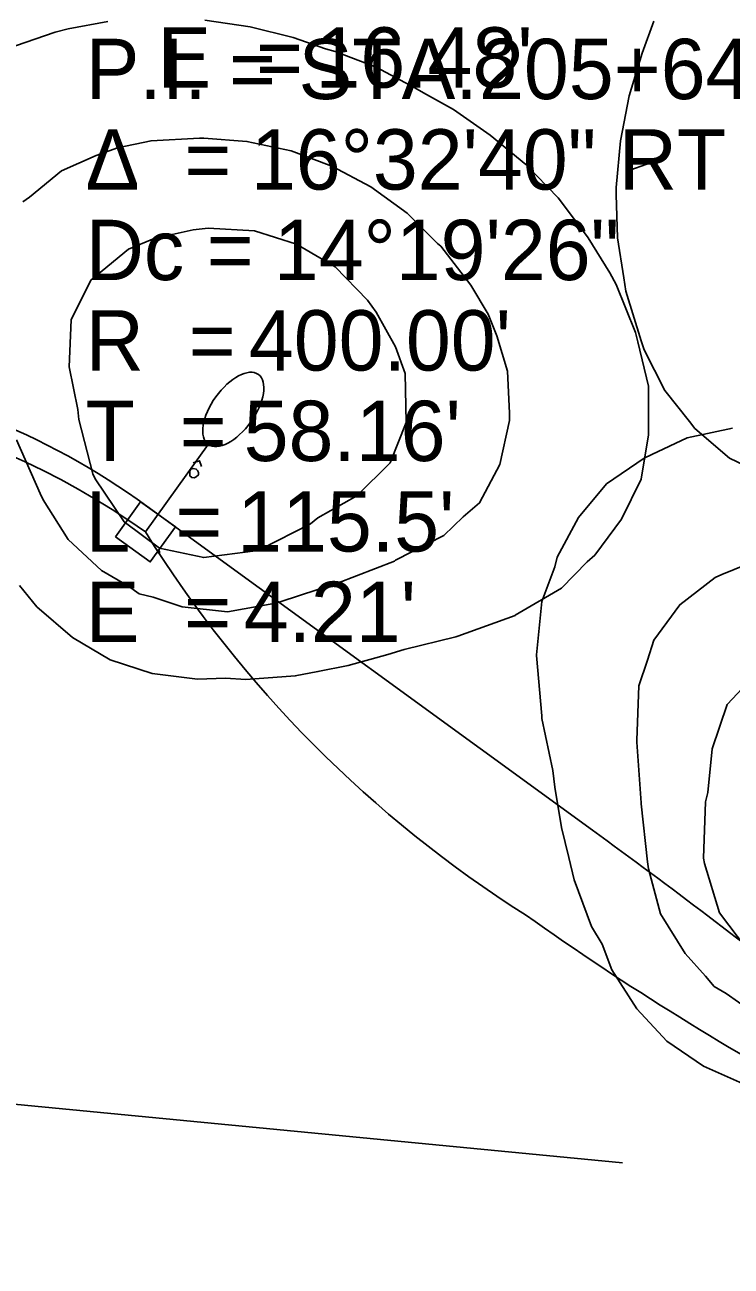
# Model space of a CAD drawing. Extents: x 1598538 to 1602183, y 285823 to 288192.
# Drawn here: x 1600950.3 to 1601032.3, y 286525.8 to 286669.9 of the extents above; entities that cross this region are included whole.
import ezdxf

# ---------------------------------------------------------------- set-up
doc = ezdxf.new("R2010")
doc.units = 0
for name, color, linetype in [('CM_Corridor_Conceptual', 7, 'Continuous'), ('Default', 7, 'Continuous'), ('MD_P_ACSC_T', 7, 'Continuous'), ('MD_P_AGB_B', 7, 'Continuous'), ('RW_P_Esmt_LA', 7, 'Continuous'), ('RW_P_Esmt_TMP', 7, 'Continuous')]:
    doc.layers.add(name, color=color, linetype=linetype)

msp = doc.modelspace()

# ---------------------------------------------------------------- linework, layer by layer
at = {"layer": 'Default'}
msp.add_line((1601016.17, 286576.42), (1600964.45, 286614.03), dxfattribs=at)
for points in [[(1600959.92, 286670.27), (1600955.3, 286669.4), (1600953.8, 286669.02), (1600948.05, 286667.05)], [(1600949.67, 286604.8), (1600951.67, 286602.33), (1600955.8, 286598.8), (1600960.17, 286596.21), (1600965.05, 286594.61), (1600970.3, 286593.96), (1600973.55, 286594.08), (1600975.92, 286593.9), (1600981.67, 286594.33), (1600984.3, 286594.83), (1600987.8, 286595.55), (1600992.42, 286596.8), (1600994.3, 286597.4), (1601000.3, 286598.86), (1601000.55, 286598.93), (1601007.17, 286601.33), (1601007.17, 286601.36), (1601012.55, 286604.49), (1601015.55, 286607.55), (1601016.42, 286608.33), (1601019.55, 286612.52), (1601021.8, 286617.15), (1601022.67, 286622.3), (1601022.67, 286623.3), (1601022.67, 286627.93), (1601021.42, 286633.08), (1601021.17, 286634.18), (1601018.92, 286639.74), (1601018.17, 286641.11), (1601015.67, 286645.18), (1601012.67, 286649.15), (1601012.17, 286649.8), (1601008.42, 286653.68), (1601004.3, 286657.08), (1601000.05, 286660.05), (1600996.55, 286661.99), (1600995.55, 286662.58), (1600991.05, 286664.96), (1600986.3, 286666.77), (1600985.17, 286667.11), (1600981.42, 286668.4), (1600976.42, 286669.65), (1600971.17, 286670.43)], [(1601023.3, 286670.3), (1601021.92, 286666.61), (1601020.42, 286661.65), (1601019.42, 286656.43), (1601018.92, 286650.99), (1601018.92, 286650.18), (1601019.05, 286645.18), (1601019.8, 286640.52), (1601020.05, 286638.99), (1601021.8, 286633.21), (1601022.17, 286632.18), (1601024.55, 286627.43), (1601027.42, 286623.83), (1601028.05, 286623.05), (1601032.05, 286619.61), (1601036.67, 286617.4)], [(1600949.3, 286621.74), (1600952.05, 286615.49), (1600952.42, 286614.74), (1600955.3, 286610.15), (1600959.17, 286606.55), (1600962.3, 286604.74), (1600963.55, 286603.86), (1600965.17, 286603.46), (1600968.55, 286602.36), (1600973.8, 286601.77), (1600979.17, 286602.74), (1600979.92, 286602.93), (1600986.42, 286605.05), (1600986.55, 286605.08), (1600993.17, 286607.65), (1600993.3, 286607.74), (1600998.92, 286610.61), (1601001.17, 286612.8), (1601003.05, 286614.4), (1601005.42, 286618.86), (1601006.55, 286623.96), (1601006.55, 286624.8), (1601006.3, 286629.68), (1601005.05, 286633.8), (1601004.05, 286636.3), (1601002.05, 286639.68), (1600998.55, 286644.18), (1600998.17, 286644.49), (1600994.67, 286648.02), (1600990.42, 286651.08), (1600985.92, 286653.46), (1600981.17, 286655.27), (1600976.05, 286656.36), (1600971.05, 286656.71), (1600970.55, 286656.74), (1600964.92, 286656.43), (1600961.05, 286655.61), (1600958.55, 286654.71), (1600954.55, 286652.93), (1600950.8, 286649.9), (1600950.05, 286649.33)], [(1601032.42, 286623.08), (1601027.17, 286621.96), (1601023.05, 286620.02), (1601022.17, 286619.61), (1601017.8, 286616.61), (1601014.55, 286612.71), (1601012.05, 286608.11), (1601011.8, 286606.99), (1601010.3, 286602.96), (1601009.67, 286596.77), (1601009.67, 286596.71), (1601010.3, 286589.71), (1601010.3, 286589.4), (1601011.55, 286583.33), (1601011.8, 286581.4), (1601012.55, 286576.74), (1601013.42, 286573.24), (1601014.05, 286570.68), (1601016.05, 286565.24), (1601017.3, 286563.18), (1601018.42, 286560.21), (1601021.3, 286555.71), (1601024.8, 286551.93), (1601029.05, 286549.02), (1601033.92, 286546.86)], [(1600969.8, 286619.05), (1600970.55, 286619.3), (1600970.8, 286618.61)], [(1600969.8, 286618.4), (1600969.55, 286618.3), (1600969.55, 286618.3), (1600969.8, 286618.4), (1600969.8, 286618.4)], [(1600970.17, 286617.43), (1600970.42, 286617.65), (1600970.42, 286617.65), (1600970.17, 286617.43), (1600970.17, 286617.43)], [(1600965.92, 286608.8), (1600965.67, 286608.9), (1600965.67, 286608.9), (1600965.92, 286608.8), (1600965.92, 286608.8)], [(1601035.67, 286607.9), (1601031.17, 286606.08), (1601030.42, 286605.74), (1601026.3, 286602.58), (1601023.3, 286598.46), (1601022.55, 286596.15), (1601021.55, 286593.18), (1601021.3, 286586.86), (1601021.3, 286586.65), (1601021.8, 286579.58), (1601021.8, 286579.49), (1601022.55, 286572.74), (1601022.67, 286571.93), (1601024.05, 286566.71), (1601026.92, 286562.11), (1601029.3, 286559.49), (1601030.3, 286558.3), (1601031.67, 286557.46), (1601034.55, 286555.46)], [(1601035.3, 286594.77), (1601031.8, 286591.02), (1601030.05, 286585.86), (1601029.55, 286580.8), (1601029.3, 286579.71), (1601029.05, 286573.18), (1601029.17, 286572.55), (1601030.92, 286566.83), (1601034.05, 286562.68)]]:
    msp.add_lwpolyline(points, dxfattribs=at)
for points in [[(1600994.42, 286629.43), (1600993.3, 286632.52), (1600991.05, 286636.52), (1600990.05, 286637.93), (1600986.3, 286641.8), (1600981.8, 286644.43), (1600976.92, 286645.99), (1600971.55, 286646.27), (1600969.8, 286646.08), (1600965.3, 286645.08), (1600962.3, 286643.86), (1600957.92, 286640.24), (1600955.67, 286635.65), (1600955.42, 286630.18), (1600956.42, 286625.24), (1600956.55, 286624.08), (1600958.17, 286617.77), (1600958.42, 286617.21), (1600961.8, 286612.21), (1600965.92, 286609.15), (1600971.05, 286608.05), (1600977.05, 286608.83), (1600977.67, 286609.02), (1600983.42, 286611.99), (1600984.3, 286612.68), (1600988.8, 286615.21), (1600992.67, 286619.05), (1600994.55, 286623.74)], [(1600969.42, 286617.8), (1600969.42, 286617.55), (1600969.67, 286617.36), (1600969.92, 286617.33), (1600970.17, 286617.43), (1600970.42, 286617.65), (1600970.42, 286617.93), (1600970.3, 286618.18), (1600970.17, 286618.33), (1600969.8, 286618.4), (1600969.55, 286618.3), (1600969.42, 286618.08)], [(1600969.42, 286617.8), (1600969.42, 286617.55), (1600969.67, 286617.36), (1600969.92, 286617.33), (1600970.17, 286617.43), (1600970.42, 286617.65), (1600970.42, 286617.93), (1600970.3, 286618.18), (1600970.17, 286618.33), (1600969.8, 286618.4), (1600969.55, 286618.3), (1600969.42, 286618.08)], [(1600969.55, 286618.3), (1600969.42, 286618.08), (1600969.42, 286618.08), (1600969.55, 286618.3)], [(1600969.42, 286618.08), (1600969.42, 286617.8), (1600969.42, 286617.8), (1600969.42, 286618.08)], [(1600969.42, 286617.8), (1600969.42, 286617.55), (1600969.42, 286617.55), (1600969.42, 286617.8)], [(1600969.42, 286617.55), (1600969.67, 286617.36), (1600969.67, 286617.36), (1600969.42, 286617.55)], [(1600969.67, 286617.36), (1600969.92, 286617.33), (1600969.92, 286617.33), (1600969.67, 286617.36)], [(1600970.17, 286618.33), (1600969.8, 286618.4), (1600969.8, 286618.4), (1600970.17, 286618.33)], [(1600969.92, 286617.33), (1600970.17, 286617.43), (1600970.17, 286617.43), (1600969.92, 286617.33)], [(1600970.3, 286618.18), (1600970.17, 286618.33), (1600970.17, 286618.33), (1600970.3, 286618.18)], [(1600970.42, 286617.93), (1600970.3, 286618.18), (1600970.3, 286618.18), (1600970.42, 286617.93)], [(1600970.42, 286617.65), (1600970.42, 286617.93), (1600970.42, 286617.93), (1600970.42, 286617.65)], [(1600965.67, 286608.68), (1600965.92, 286608.58), (1600965.92, 286608.8), (1600965.67, 286608.9)], [(1600965.67, 286608.68), (1600965.92, 286608.58), (1600965.92, 286608.8), (1600965.67, 286608.9)], [(1600965.67, 286608.9), (1600965.67, 286608.68), (1600965.67, 286608.68), (1600965.67, 286608.9)], [(1600965.67, 286608.68), (1600965.92, 286608.58), (1600965.92, 286608.58), (1600965.67, 286608.68)], [(1600965.92, 286608.58), (1600965.92, 286608.8), (1600965.92, 286608.8), (1600965.92, 286608.58)]]:
    msp.add_lwpolyline(points, close=True, dxfattribs=at)
for centre, radius, start, end in [((1600914.17, 286544.87), 85.5, 53.985, 111.5214), ((1600554.3, 285941.06), 785.5, 51.55039, 53.98502)]:
    msp.add_arc(centre, radius, start, end, dxfattribs=at)
at = {"layer": 'MD_P_ACSC_T'}
msp.add_line((1600658.66, 286572.61), (1601019.64, 286537.81), dxfattribs=at)
at = {"layer": 'MD_P_AGB_B'}
msp.add_line((1601020.06, 286652.85), (1601022.89, 286653.86), dxfattribs=at)
at = {"layer": 'RW_P_Esmt_LA'}
msp.add_line((1600964.27, 286611.04), (1600971.56, 286621.19), dxfattribs=at)
msp.add_lwpolyline([(1600960.78, 286610.46), (1600963.7, 286614.52), (1600967.76, 286611.61), (1600964.84, 286607.55)], close=True, dxfattribs=at)
msp.add_ellipse((1600974.47, 286625.25), major_axis=(2.91, 4.06), ratio=0.5, dxfattribs=at)
at = {"layer": 'RW_P_Esmt_TMP'}
for centre, radius, start, end in [((1600912.87, 286538.67), 88.77, 54.6144, 101.9791), ((1601083.43, 286685.21), 140.36, 211.9008, 237.6837), ((1601214.78, 286858.3), 357.34, 234.7208, 248.4986)]:
    msp.add_arc(centre, radius, start, end, dxfattribs=at)

# ---------------------------------------------------------------- texts
at = {"layer": 'CM_Corridor_Conceptual'}
for s, p in [('E  = ', (1600965.66, 286662.59)), ("16.48'", (1600984.01, 286662.59)), ('P.I. = STA. ', (1600957.33, 286661.26)), ('205+64.12', (1601003, 286661.26)), ('Δ  = ', (1600957.33, 286650.76)), ('16°32\'40" RT', (1600976.52, 286650.76)), ('Dc = ', (1600957.33, 286640.26)), ('14°19\'26"', (1600979.18, 286640.26)), ('R  = ', (1600957.33, 286629.76)), ("400.00'", (1600976.29, 286629.76)), ('T  = ', (1600957.33, 286619.26)), ("58.16'", (1600975.68, 286619.26)), ('L  = ', (1600957.33, 286608.76)), ("115.5'", (1600974.93, 286608.76)), ('E  = ', (1600957.33, 286598.26)), ("4.21'", (1600975.68, 286598.26))]:
    msp.add_text(s, height=7, dxfattribs=at).set_placement(p)

doc.saveas('drawing.dxf')
